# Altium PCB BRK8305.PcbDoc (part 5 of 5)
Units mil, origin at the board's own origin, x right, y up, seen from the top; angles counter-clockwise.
Board outline 5944.89 x 4139.76 mil, 4 copper layers (L1-Top, L2-GND, L3-GND, L4-BOT), stack 61.2 mil thick; 237 components, 286 nets, 1257 pads, 698 vias.
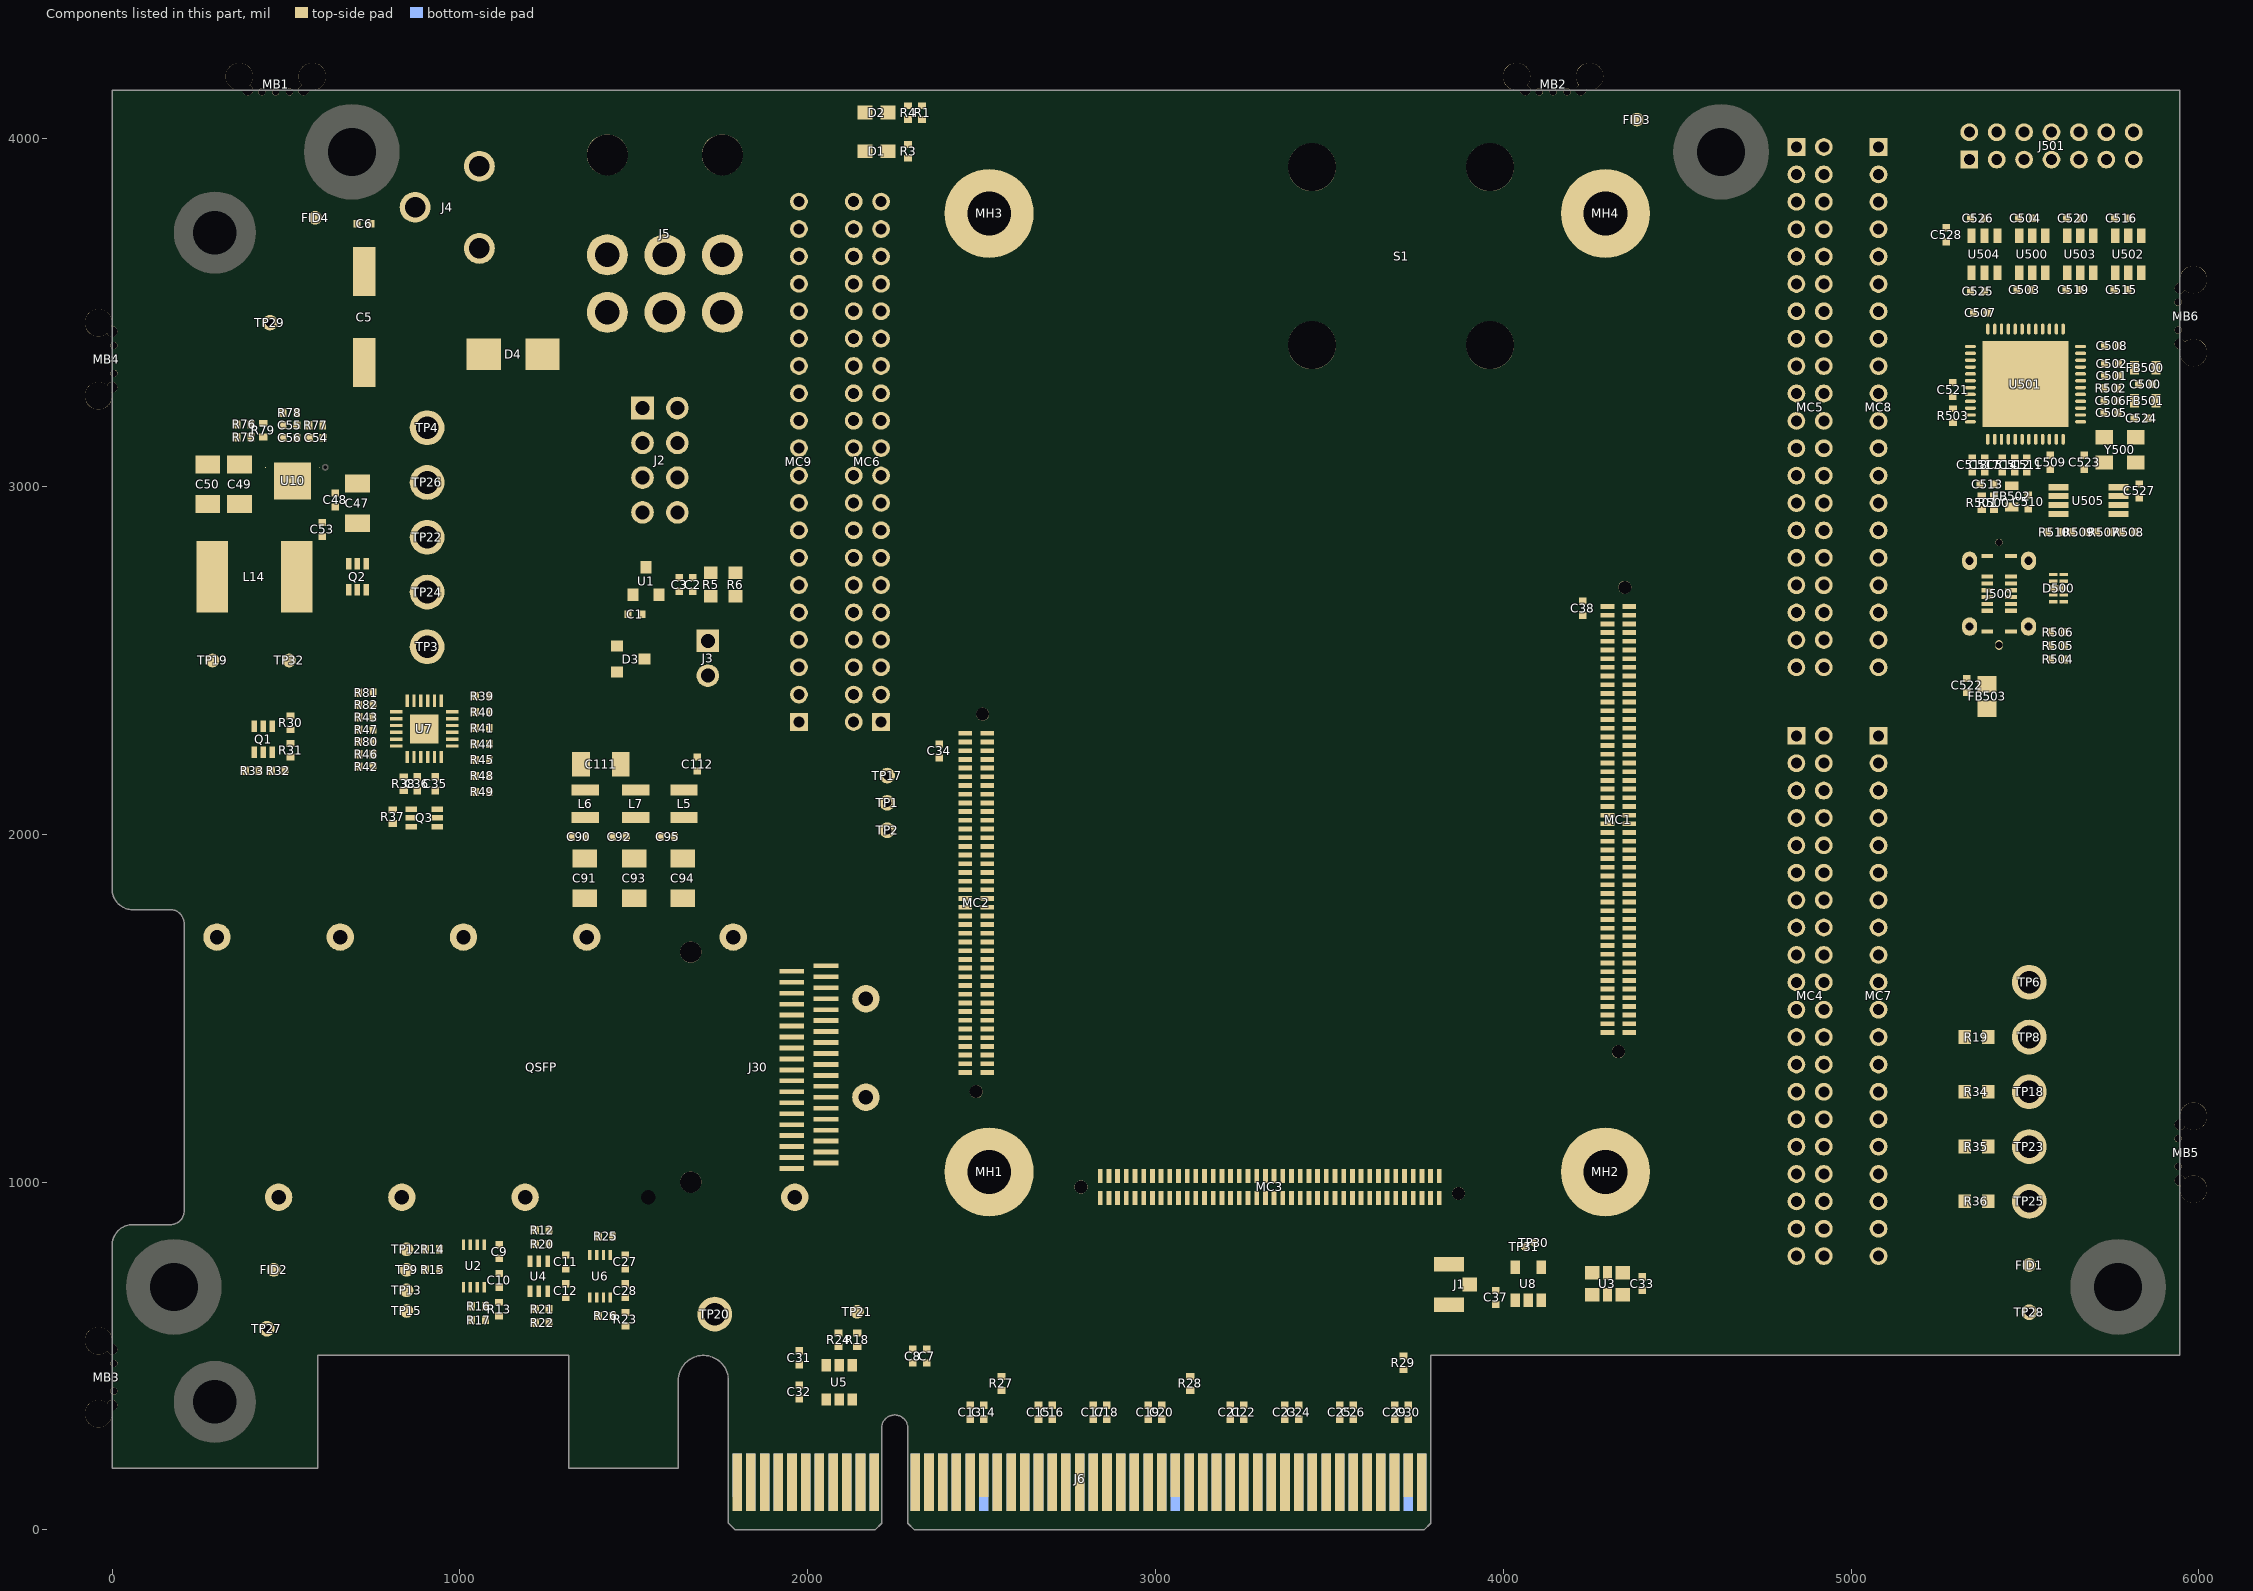
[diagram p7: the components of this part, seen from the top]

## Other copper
L1-Top:
  region net DGND: 1188.23,3425.29 1218.2,3425.29 1254.13,3461.22 1324.92,3461.22 1334.65,3451.49 1334.65,3301.57 1324.5,3291.43 1259.84,3291.43 1216.54,3334.74 1188.23,3334.74
  region net +VDCIN: 670.7,3503.97 775.77,3503.97 804.57,3532.77 804.57,3701.38 777.24,3728.7 670.04,3728.7 643.16,3701.82 643.16,3531.51
  region net NetC53_2: 614.15,2638.61 614.15,2865.61 595.15,2865.61 538.96,2921.81 538.96,2953.61 474,2953.61 474,2638.61
  region net DGND: 560.67,3058.65 560.67,2972.36 414.15,2972.36 414.15,3009.76 480.28,3009.76 480.28,3058.65
  region net +VDCIN: 740.15,3067.61 631.15,3067.61 631.15,3036.34 579.69,3036.34 579.69,2971.38 740.15,2971.38
  region net DGND: 670.7,3242.15 775.77,3242.15 804.57,3270.96 804.57,3439.57 777.24,3466.89 670.04,3466.89 643.16,3440.01 643.16,3269.7
L4-BOT:
  pour cut-out: 1056.58,3755.47 cw(c1056.58,3684.6) 1127.44,3684.6 cw(c1056.58,3684.6) 1056.58,3613.73 cw(c1056.58,3684.6) 985.71,3684.6 cw(c1056.58,3684.6)

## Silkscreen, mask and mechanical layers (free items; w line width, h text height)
Top Overlay:
  circle w22: c1122.85,3569.62 r11
  region: 5877.95,1994.09 5216.95,1994.09 5216.95,1679.13 5877.95,1679.13
  lines w10: 2364.17,2188.98 2364.17,872.05 4450.79,872.05 4450.79,4118.11 ; 2364.17,2291.34 2364.17,4118.11
  lines w15.75: 1034.85,3569.62 1082.85,3569.62 ; 1122.85,3569.62 1184.85,3569.62 ; 1136.53,3532.03 cw(c1122.85,3569.62) 1136.53,3607.2
  lines w20: 5253.94,1102.36 5285.43,1102.36 ; 5253.94,1259.84 5285.43,1259.84 ; 5253.94,1417.32 5285.43,1417.32 ; 5285.43,944.88 5253.94,944.88 5253.94,1525.59 5303.15,1574.8 5437.01,1574.8 ; 5431.1,944.88 5444.88,944.88 ; 5431.1,1102.36 5444.88,1102.36 ; 5431.1,1258.78 5444.88,1258.78 ; 5431.1,1417.32 5444.88,1417.32
  text "DGND" at 5137.8,3996.68 h30 r270
  text "5-15 VDC" at 293.89,3912 h100
  text "JTAG HEADER" at 5375.38,3791.32 h60
  text "+" at 1197.85,3608.61 h70 r270
  text "-" at 942.85,3534.62 h70
  text "TESTING ONLY" at 3581.9,3449.8 h60
  text "SYSMON" at 1423.07,3342.72 h80
  text "VP" at 1386.71,3204.88 h50
  text "VCCADC" at 1687.88,3198.9 h50
  text "VN" at 1385.76,3104.88 h50
  text "GNDADC" at 1252.66,2904.88 h50
  text "VREFP" at 1687.88,2898.9 h50
  text "USB JTAG" at 5295.23,2463.78 h100 r90
  text "+" at 1838.09,2305.77 h80 r90
  text "DGND" at 5137.8,2303.77 h30 r270
  text "DGND" at 1917.32,2296.4 h30 r90
  text "'.Part_Number' '.PCB_Revision'XX" at 5343.85,2039.5 h40
  text "3V3" at 3731.33,760.22 h40 r270
  text "224 REFCLK0" at 3776.41,549.9 h60
Top Solder:
  rectangle: 1312.98,177.16 1627.94,312.99
Solder Side:
  rectangle: 1312.98,177.16 1627.94,312.99
Dimensions:
  rectangle: 1781.49,9.84 3781.49,56.93
  lines w1: 4526.47,-267.17 4547.19,-321.84 4567.68,-321.84 4588.52,-266.87 ; 4526.83,-267.19 4526.83,28.16
  lines w2: 4588.43,-266.84 4588.43,-25.42 ; 4638.85,-134.01 4687.73,-5.23
  lines w10: 3781.49,9.84 4220.47,-515.75 ; 3781.49,56.93 4343.78,350.39 ; 5349.4,-145.34 cw(c4724.4,-145.34) 5349.4,-143.92
  text "EDGE BEVEL" at 4455.01,340.55 h50
  text "ACROSS PADS" at 4586.74,-588.49 h50
  text "ALL UNITS IN MILLIMETERS UNLESS OTHERWISE SPECIFIED" at 708.66,-629.92 h60
Outline:
  lines w3.94: -0.01,177.16 -0.01,818.9 cw(c59.06,818.9) 59.06,877.95 167.46,877.95 ccw(c167.46,917.32) 206.83,917.32 206.83,1744.09 ccw(c167.46,1744.09) 167.46,1783.46 59.06,1783.46 cw(c59.06,1842.52) 0,1842.52 -0.01,4139.76 5944.88,4139.76 5944.88,501.97 3791.33,501.97 3791.33,19.68 3771.65,0 2307.08,0 2287.39,19.68 2287.39,293.31 ccw(c2249.99,293.31) 2212.59,293.31 2212.59,19.68 2192.91,0 1791.33,0 1771.65,19.68 1771.65,430.12 ccw(c1699.8,430.12) 1627.94,430.12 1627.94,177.16 1312.98,177.16 1312.98,501.97 590.54,501.97 590.54,177.16 -0.01,177.16
  lines w11.81: 2364.17,872.05 2364.17,4139.76 4450.79,4139.76 4450.79,872.05 2364.17,872.05
Fab Notes:
  drawing of 90 lines, arcs and shapes, not listed
  text "LAYER STACKUP TABLE" at 7244.09,7330.71 h80
  text "S" at 12600.61,7229.28 h79.46
  text "i" at 12632.47,7229.28 h79.46
  text "n" at 12650.67,7229.28 h79.46
  text "g" at 12687.08,7229.27 h79.46
  text "l" at 12718.94,7229.28 h79.46
  text "e" at 12737.14,7229.28 h79.46
  text "-" at 12773.55,7229.3 h79.46
  text "D" at 10138.59,7138.26 h79.46
  text "i" at 10179.55,7138.26 h79.46
  text "f" at 10197.75,7138.26 h79.46
  text "f" at 10220.51,7138.26 h79.46
  text "e" at 10243.26,7138.26 h79.46
  text "r" at 10279.67,7138.26 h79.46
  text "e" at 10302.43,7138.26 h79.46
  text "n" at 10338.83,7138.26 h79.46
  text "t" at 10375.24,7138.26 h79.46
  text "i" at 10398,7138.26 h79.46
  text "a" at 10416.2,7138.26 h79.46
  text "l" at 10448.06,7138.26 h79.46
  text "D" at 10515.61,7138.26 h79.46
  text "i" at 10556.57,7138.26 h79.46
  text "f" at 10574.78,7138.26 h79.46
  text "f" at 10597.53,7138.26 h79.46
  text "e" at 10620.29,7138.26 h79.46
  text "r" at 10656.7,7138.26 h79.46
  text "e" at 10679.45,7138.26 h79.46
  text "n" at 10715.86,7138.26 h79.46
  text "t" at 10752.27,7138.26 h79.46
  text "i" at 10775.02,7138.26 h79.46
  text "a" at 10793.23,7138.26 h79.46
  text "l" at 10825.08,7138.26 h79.46
  text "D" at 10938.06,7138.26 h79.46
  text "i" at 10979.02,7138.26 h79.46
  text "f" at 10997.23,7138.26 h79.46
  text "f" at 11019.98,7138.26 h79.46
  text "e" at 11042.74,7138.26 h79.46
  text "r" at 11079.15,7138.26 h79.46
  text "e" at 11101.9,7138.26 h79.46
  text "n" at 11138.31,7138.26 h79.46
  text "t" at 11174.72,7138.26 h79.46
  text "i" at 11197.47,7138.26 h79.46
  text "a" at 11215.68,7138.26 h79.46
  text "l" at 11247.53,7138.26 h79.46
  text "D" at 11315.09,7138.26 h79.46
  text "i" at 11356.05,7138.26 h79.46
  text "f" at 11374.25,7138.26 h79.46
  text "f" at 11397.01,7138.26 h79.46
  text "e" at 11419.76,7138.26 h79.46
  text "r" at 11456.17,7138.26 h79.46
  text "e" at 11478.93,7138.26 h79.46
  text "n" at 11515.33,7138.26 h79.46
  text "t" at 11551.74,7138.26 h79.46
  text "i" at 11574.5,7138.26 h79.46
  text "a" at 11592.7,7138.26 h79.46
  text "l" at 11624.56,7138.26 h79.46
  text "D" at 11737.54,7138.26 h79.46
  text "i" at 11778.5,7138.26 h79.46
  text "f" at 11796.7,7138.26 h79.46
  text "f" at 11819.46,7138.26 h79.46
  text "e" at 11842.21,7138.26 h79.46
  text "r" at 11878.62,7138.26 h79.46
  text "e" at 11901.38,7138.26 h79.46
  text "n" at 11937.78,7138.26 h79.46
  text "t" at 11974.19,7138.26 h79.46
  text "i" at 11996.95,7138.26 h79.46
  text "a" at 12015.15,7138.26 h79.46
  text "l" at 12047.01,7138.26 h79.46
  text "D" at 12114.56,7138.26 h79.46
  text "i" at 12155.52,7138.26 h79.46
  text "f" at 12173.73,7138.26 h79.46
  text "f" at 12196.48,7138.26 h79.46
  text "e" at 12219.24,7138.26 h79.46
  text "r" at 12255.65,7138.26 h79.46
  text "e" at 12278.4,7138.26 h79.46
  text "n" at 12314.81,7138.26 h79.46
  text "t" at 12351.22,7138.26 h79.46
  text "i" at 12373.97,7138.26 h79.46
  text "a" at 12392.18,7138.26 h79.46
  text "l" at 12424.03,7138.26 h79.46
  text "E" at 12609.69,7138.26 h79.46
  text "n" at 12641.55,7138.26 h79.46
  text "d" at 12677.96,7138.26 h79.46
  text "e" at 12714.37,7138.26 h79.46
  text "d" at 12750.78,7138.26 h79.46
  text "T" at 10229.44,7047.24 h79.46
  text "r" at 10261.3,7047.24 h79.46
  text "a" at 10284.05,7047.24 h79.46
  text "c" at 10315.91,7047.24 h79.46
  text "e" at 10343.21,7047.24 h79.46
  text "T" at 10606.46,7047.24 h79.46
  text "r" at 10638.32,7047.24 h79.46
  text "a" at 10661.08,7047.24 h79.46
  text "c" at 10692.93,7047.24 h79.46
  text "e" at 10720.24,7047.24 h79.46
  text "T" at 11028.91,7047.24 h79.46
  text "r" at 11060.77,7047.24 h79.46
  text "a" at 11083.53,7047.24 h79.46
  text "c" at 11115.38,7047.24 h79.46
  text "e" at 11142.69,7047.24 h79.46
  text "T" at 11405.94,7047.24 h79.46
  text "r" at 11437.8,7047.24 h79.46
  text "a" at 11460.55,7047.24 h79.46
  text "c" at 11492.41,7047.24 h79.46
  text "e" at 11519.71,7047.24 h79.46
  text "T" at 11828.39,7047.24 h79.46
  text "r" at 11860.25,7047.24 h79.46
  text "a" at 11883,7047.24 h79.46
  text "c" at 11914.86,7047.24 h79.46
  text "e" at 11942.16,7047.24 h79.46
  text "T" at 12205.41,7047.24 h79.46
  text "r" at 12237.27,7047.24 h79.46
  text "a" at 12260.03,7047.24 h79.46
  text "c" at 12291.88,7047.24 h79.46
  text "e" at 12319.19,7047.24 h79.46
  text "T" at 12623.32,7047.24 h79.46
  text "r" at 12655.18,7047.24 h79.46
  text "a" at 12677.93,7047.24 h79.46
  text "c" at 12709.79,7047.24 h79.46
  text "e" at 12737.1,7047.24 h79.46
  text "S" at 12891.33,7047.24 h79.46
  text "i" at 12923.18,7047.24 h79.46
  text "n" at 12941.39,7047.24 h79.46
  text "g" at 12977.8,7047.23 h79.46
  text "l" at 13009.65,7047.24 h79.46
  text "e" at 13027.86,7047.24 h79.46
  text "-" at 13064.27,7047.26 h79.46
  text "E" at 13087.02,7047.24 h79.46
  text "n" at 13118.88,7047.24 h79.46
  text "d" at 13155.29,7047.24 h79.46
  text "e" at 13191.69,7047.24 h79.46
  text "d" at 13228.1,7047.24 h79.46
  text "M" at 9357.28,7045.9 h75.05
  text "a" at 9407.35,7045.9 h75.05
  text "t" at 9443.75,7045.9 h75.05
  text "e" at 9461.96,7045.9 h75.05
  text "r" at 9498.37,7045.9 h75.05
  text "i" at 9521.12,7045.9 h75.05
  text "a" at 9534.77,7045.9 h75.05
  text "l" at 9571.18,7045.9 h75.05
  text "G" at 8089.94,6959.43 h75.05
  text "e" at 8140,6959.43 h75.05
  text "r" at 8176.41,6959.43 h75.05
  text "b" at 8199.16,6959.43 h75.05
  text "e" at 8235.57,6959.43 h75.05
  text "r" at 8271.98,6959.43 h75.05
  text "M" at 8830.36,6959.43 h75.05
  text "a" at 8880.42,6959.43 h75.05
  text "t" at 8916.83,6959.43 h75.05
  text "e" at 8935.03,6959.43 h75.05
  text "r" at 8971.44,6959.43 h75.05
  text "i" at 8994.2,6959.43 h75.05
  text "a" at 9007.85,6959.43 h75.05
  text "l" at 9044.26,6959.43 h75.05
  text "T" at 9316.4,6959.43 h75.05
  text "h" at 9357.36,6959.43 h75.05
  text "i" at 9393.77,6959.43 h75.05
  text "c" at 9407.42,6959.43 h75.05
  text "k" at 9443.83,6959.43 h75.05
  text "n" at 9475.69,6959.43 h75.05
  text "e" at 9512.1,6959.43 h75.05
  text "s" at 9548.51,6959.43 h75.05
  text "s" at 9584.91,6959.43 h75.05
  text "C" at 9766.11,6956.22 h79.46
  text "o" at 9802.52,6956.22 h79.46
  text "p" at 9838.92,6956.21 h79.46
  text "p" at 9875.33,6956.21 h79.46
  text "e" at 9911.74,6956.22 h79.46
  text "r" at 9948.15,6956.22 h79.46
  text "I" at 10147.67,6956.22 h79.46
  text "m" at 10165.88,6956.22 h79.46
  text "p" at 10220.49,6956.21 h79.46
  text "e" at 10256.9,6956.22 h79.46
  text "d" at 10293.31,6956.22 h79.46
  text "a" at 10329.72,6956.22 h79.46
  text "n" at 10361.57,6956.22 h79.46
  text "c" at 10397.98,6956.22 h79.46
  text "e" at 10425.29,6956.22 h79.46
  text "W" at 10497.44,6956.22 h79.46
  text "i" at 10556.61,6956.22 h79.46
  text "d" at 10574.81,6956.22 h79.46
  text "t" at 10611.22,6956.22 h79.46
  text "h" at 10633.98,6956.22 h79.46
  text "/" at 10670.38,6956.21 h79.46
  text "S" at 10697.69,6956.22 h79.46
  text "p" at 10729.55,6956.21 h79.46
  text "a" at 10765.96,6956.22 h79.46
  text "c" at 10797.81,6956.22 h79.46
  text "e" at 10825.12,6956.22 h79.46
  text "I" at 10947.15,6956.22 h79.46
  text "m" at 10965.35,6956.22 h79.46
  text "p" at 11019.97,6956.21 h79.46
  text "e" at 11056.37,6956.22 h79.46
  text "d" at 11092.78,6956.22 h79.46
  text "a" at 11129.19,6956.22 h79.46
  text "n" at 11161.05,6956.22 h79.46
  text "c" at 11197.46,6956.22 h79.46
  text "e" at 11224.76,6956.22 h79.46
  text "W" at 11296.92,6956.22 h79.46
  text "i" at 11356.08,6956.22 h79.46
  text "d" at 11374.29,6956.22 h79.46
  text "t" at 11410.7,6956.22 h79.46
  text "h" at 11433.45,6956.22 h79.46
  text "/" at 11469.86,6956.21 h79.46
  text "S" at 11497.16,6956.22 h79.46
  text "p" at 11529.02,6956.21 h79.46
  text "a" at 11565.43,6956.22 h79.46
  text "c" at 11597.29,6956.22 h79.46
  text "e" at 11624.59,6956.22 h79.46
  text "I" at 11746.62,6956.22 h79.46
  text "m" at 11764.83,6956.22 h79.46
  text "p" at 11819.44,6956.21 h79.46
  text "e" at 11855.85,6956.22 h79.46
  text "d" at 11892.26,6956.22 h79.46
  text "a" at 11928.67,6956.22 h79.46
  text "n" at 11960.52,6956.22 h79.46
  text "c" at 11996.93,6956.22 h79.46
  text "e" at 12024.24,6956.22 h79.46
  text "W" at 12096.39,6956.22 h79.46
  text "i" at 12155.56,6956.22 h79.46
  text "d" at 12173.76,6956.22 h79.46
  text "t" at 12210.17,6956.22 h79.46
  text "h" at 12232.93,6956.22 h79.46
  text "/" at 12269.33,6956.21 h79.46
  text "S" at 12296.64,6956.22 h79.46
  text "p" at 12328.5,6956.21 h79.46
  text "a" at 12364.9,6956.22 h79.46
  text "c" at 12396.76,6956.22 h79.46
  text "e" at 12424.07,6956.22 h79.46
  text "I" at 12541.56,6956.22 h79.46
  text "m" at 12559.76,6956.22 h79.46
  text "p" at 12614.37,6956.21 h79.46
  text "e" at 12650.78,6956.22 h79.46
  text "d" at 12687.19,6956.22 h79.46
  text "a" at 12723.6,6956.22 h79.46
  text "n" at 12755.45,6956.22 h79.46
  text "c" at 12791.86,6956.22 h79.46
  text "e" at 12819.17,6956.22 h79.46
  text "T" at 12909.5,6956.22 h79.46
  text "r" at 12941.35,6956.22 h79.46
  text "a" at 12964.11,6956.22 h79.46
  text "c" at 12995.97,6956.22 h79.46
  text "e" at 13023.27,6956.22 h79.46
  text "W" at 13073.33,6956.22 h79.46
  text "i" at 13132.5,6956.22 h79.46
  text "d" at 13150.7,6956.22 h79.46
  text "t" at 13187.11,6956.22 h79.46
  text "h" at 13209.86,6956.22 h79.46
  text "L" at 7217.78,6872.96 h75.05
  text "a" at 7254.19,6872.96 h75.05
  text "y" at 7290.6,6872.95 h75.05
  text "e" at 7322.46,6872.96 h75.05
  text "r" at 7358.86,6872.96 h75.05
  text "L" at 7444.91,6872.96 h75.05
  text "a" at 7481.31,6872.96 h75.05
  text "y" at 7517.72,6872.95 h75.05
  text "e" at 7549.58,6872.96 h75.05
  text "r" at 7585.99,6872.96 h75.05
  text "N" at 7626.95,6872.96 h75.05
  text "a" at 7672.46,6872.96 h75.05
  text "m" at 7708.86,6872.96 h75.05
  text "e" at 7768.03,6872.96 h75.05
  text "L" at 8089.94,6872.96 h75.05
  text "a" at 8126.34,6872.96 h75.05
  text "y" at 8162.75,6872.95 h75.05
  text "e" at 8194.61,6872.96 h75.05
  text "r" at 8231.02,6872.96 h75.05
  text "M" at 8362.48,6872.96 h75.05
  text "a" at 8412.55,6872.96 h75.05
  text "t" at 8448.95,6872.96 h75.05
  text "e" at 8467.16,6872.96 h75.05
  text "r" at 8503.57,6872.96 h75.05
  text "i" at 8526.32,6872.96 h75.05
  text "a" at 8539.97,6872.96 h75.05
  text "l" at 8576.38,6872.96 h75.05
  text "T" at 8608.24,6872.96 h75.05
  text "y" at 8649.2,6872.95 h75.05
  text "p" at 8681.06,6872.95 h75.05
  text "e" at 8717.46,6872.96 h75.05
  text "C" at 8830.36,6872.96 h75.05
  text "o" at 8880.42,6872.96 h75.05
  text "n" at 8916.83,6872.96 h75.05
  text "s" at 8953.24,6872.96 h75.05
  text "t" at 8989.64,6872.96 h75.05
  text "r" at 9007.85,6872.96 h75.05
  text "u" at 9030.6,6872.96 h75.05
  text "c" at 9067.01,6872.96 h75.05
  text "t" at 9103.42,6872.96 h75.05
  text "i" at 9121.62,6872.96 h75.05
  text "o" at 9135.28,6872.96 h75.05
  text "n" at 9171.69,6872.96 h75.05
  text "(" at 9389.08,6872.95 h75.05
  text "m" at 9411.84,6872.96 h75.05
  text "m" at 9471,6872.96 h75.05
  text ")" at 9530.16,6872.95 h75.05
  text "W" at 9702.51,6865.2 h79.46
  text "e" at 9761.68,6865.2 h79.46
  text "i" at 9798.08,6865.2 h79.46
  text "g" at 9816.29,6865.19 h79.46
  text "h" at 9848.15,6865.2 h79.46
  text "t" at 9884.55,6865.2 h79.46
  text "(" at 9920.96,6865.19 h79.46
  text "o" at 9943.72,6865.2 h79.46
  text "z" at 9980.13,6865.2 h79.46
  text ")" at 10007.43,6865.19 h79.46
  text "(" at 10202.18,6865.19 h79.46
  text "o" at 10224.94,6865.2 h79.46
  text "h" at 10261.35,6865.2 h79.46
  text "m" at 10297.76,6865.2 h79.46
  text "s" at 10352.37,6865.2 h79.46
  text ")" at 10379.67,6865.19 h79.46
  text "(" at 10597.38,6865.19 h79.46
  text "m" at 10620.13,6865.2 h79.46
  text "i" at 10674.75,6865.2 h79.46
  text "l" at 10692.95,6865.2 h79.46
  text "s" at 10711.15,6865.2 h79.46
  text ")" at 10738.46,6865.19 h79.46
  text "(" at 11001.66,6865.19 h79.46
  text "o" at 11024.41,6865.2 h79.46
  text "h" at 11060.82,6865.2 h79.46
  text "m" at 11097.23,6865.2 h79.46
  text "s" at 11151.84,6865.2 h79.46
  text ")" at 11179.15,6865.19 h79.46
  text "(" at 11396.85,6865.19 h79.46
  text "m" at 11419.61,6865.2 h79.46
  text "i" at 11474.22,6865.2 h79.46
  text "l" at 11492.43,6865.2 h79.46
  text "s" at 11510.63,6865.2 h79.46
  text ")" at 11537.94,6865.19 h79.46
  text "(" at 11801.13,6865.19 h79.46
  text "o" at 11823.89,6865.2 h79.46
  text "h" at 11860.3,6865.2 h79.46
  text "m" at 11896.71,6865.2 h79.46
  text "s" at 11951.32,6865.2 h79.46
  text ")" at 11978.62,6865.19 h79.46
  text "(" at 12196.33,6865.19 h79.46
  text "m" at 12219.08,6865.2 h79.46
  text "i" at 12273.7,6865.2 h79.46
  text "l" at 12291.9,6865.2 h79.46
  text "s" at 12310.1,6865.2 h79.46
  text ")" at 12337.41,6865.19 h79.46
  text "(" at 12600.61,6865.19 h79.46
  text "o" at 12623.36,6865.2 h79.46
  text "h" at 12659.77,6865.2 h79.46
  text "m" at 12696.18,6865.2 h79.46
  text "s" at 12750.79,6865.2 h79.46
  text ")" at 12778.1,6865.19 h79.46
  text "(" at 12995.8,6865.19 h79.46
  text "m" at 13018.56,6865.2 h79.46
  text "i" at 13073.17,6865.2 h79.46
  text "l" at 13091.37,6865.2 h79.46
  text "s" at 13109.58,6865.2 h79.46
  text ")" at 13136.89,6865.19 h79.46
  text "O" at 7444.91,6736.43 h75.05
  text "v" at 7499.52,6736.43 h75.05
  text "e" at 7531.37,6736.43 h75.05
  text "r" at 7567.78,6736.43 h75.05
  text "l" at 7590.54,6736.43 h75.05
  text "a" at 7604.19,6736.43 h75.05
  text "y" at 7640.6,6736.42 h75.05
  text "T" at 7690.66,6736.43 h75.05
  text "o" at 7731.62,6736.43 h75.05
  text "p" at 7768.03,6736.42 h75.05
  text "G" at 8089.94,6736.43 h75.05
  text "T" at 8140,6736.43 h75.05
  text "O" at 8180.96,6736.43 h75.05
  text "S" at 8362.48,6736.43 h75.05
  text "i" at 8407.99,6736.43 h75.05
  text "l" at 8421.65,6736.43 h75.05
  text "k" at 8435.3,6736.43 h75.05
  text "s" at 8467.16,6736.43 h75.05
  text "c" at 8503.57,6736.43 h75.05
  text "r" at 8539.97,6736.43 h75.05
  text "e" at 8562.73,6736.43 h75.05
  text "e" at 8599.14,6736.43 h75.05
  text "n" at 8635.55,6736.43 h75.05
  text "S" at 7444.91,6645.41 h75.05
  text "o" at 7490.42,6645.41 h75.05
  text "l" at 7526.82,6645.41 h75.05
  text "d" at 7540.48,6645.41 h75.05
  text "e" at 7576.88,6645.41 h75.05
  text "r" at 7613.29,6645.41 h75.05
  text "M" at 7654.25,6645.41 h75.05
  text "a" at 7704.31,6645.41 h75.05
  text "s" at 7740.72,6645.41 h75.05
  text "k" at 7777.13,6645.41 h75.05
  text "T" at 7827.19,6645.41 h75.05
  text "o" at 7868.15,6645.41 h75.05
  text "p" at 7904.56,6645.4 h75.05
  text "G" at 8089.94,6645.41 h75.05
  text "T" at 8140,6645.41 h75.05
  text "S" at 8180.96,6645.41 h75.05
  text "S" at 8362.48,6645.41 h75.05
  text "o" at 8407.99,6645.41 h75.05
  text "l" at 8444.4,6645.41 h75.05
  text "d" at 8458.06,6645.41 h75.05
  text "e" at 8494.46,6645.41 h75.05
  text "r" at 8530.87,6645.41 h75.05
  text "R" at 8571.83,6645.41 h75.05
  text "e" at 8621.89,6645.41 h75.05
  text "s" at 8658.3,6645.41 h75.05
  text "i" at 8694.71,6645.41 h75.05
  text "s" at 8708.36,6645.41 h75.05
  text "t" at 8744.77,6645.41 h75.05
  text "1" at 7217.78,6554.39 h75.05
  text "L" at 7444.91,6554.39 h75.05
  text "1" at 7481.31,6554.39 h75.05
  text "-" at 7517.72,6554.4 h75.05
  text "T" at 7540.48,6554.39 h75.05
  text "O" at 7581.44,6554.39 h75.05
  text "P" at 7636.05,6554.39 h75.05
  text "G" at 8089.94,6554.39 h75.05
  text "T" at 8140,6554.39 h75.05
  text "L" at 8180.96,6554.39 h75.05
  text "C" at 8362.48,6554.39 h75.05
  text "o" at 8412.55,6554.39 h75.05
  text "p" at 8448.95,6554.38 h75.05
  text "p" at 8485.36,6554.38 h75.05
  text "e" at 8521.77,6554.39 h75.05
  text "r" at 8558.18,6554.39 h75.05
  text "0" at 9697.97,6551.18 h79.46
  text "." at 9729.83,6551.18 h79.46
  text "5" at 9748.03,6551.18 h79.46
  text "+" at 9793.54,6551.18 h79.46
  text "p" at 9839.05,6551.17 h79.46
  text "l" at 9875.46,6551.18 h79.46
  text "a" at 9893.66,6551.18 h79.46
  text "t" at 9925.52,6551.18 h79.46
  text "i" at 9948.28,6551.18 h79.46
  text "n" at 9966.48,6551.18 h79.46
  text "g" at 10002.89,6551.17 h79.46
  text "8" at 10270.32,6551.18 h79.46
  text "5" at 10302.18,6551.18 h79.46
  text "7" at 10538.33,6551.18 h79.46
  text "." at 10570.18,6551.18 h79.46
  text "5" at 10588.39,6551.18 h79.46
  text "0" at 10620.25,6551.18 h79.46
  text "/" at 10665.76,6551.17 h79.46
  text "6" at 10706.72,6551.18 h79.46
  text "." at 10738.57,6551.18 h79.46
  text "0" at 10756.78,6551.18 h79.46
  text "0" at 10788.63,6551.18 h79.46
  text "9" at 11069.8,6551.18 h79.46
  text "0" at 11101.65,6551.18 h79.46
  text "5" at 11337.8,6551.18 h79.46
  text "." at 11369.66,6551.18 h79.46
  text "6" at 11387.86,6551.18 h79.46
  text "0" at 11419.72,6551.18 h79.46
  text "/" at 11465.23,6551.17 h79.46
  text "6" at 11506.19,6551.18 h79.46
  text "." at 11538.05,6551.18 h79.46
  text "0" at 11556.25,6551.18 h79.46
  text "0" at 11588.11,6551.18 h79.46
  text "1" at 11855.64,6551.18 h79.46
  text "0" at 11887.5,6551.18 h79.46
  text "0" at 11919.36,6551.18 h79.46
  text "5" at 12137.28,6551.18 h79.46
  text "." at 12169.13,6551.18 h79.46
  text "2" at 12187.34,6551.18 h79.46
  text "5" at 12219.19,6551.18 h79.46
  text "/" at 12264.71,6551.17 h79.46
  text "6" at 12305.66,6551.18 h79.46
  text "." at 12337.52,6551.18 h79.46
  text "0" at 12355.73,6551.18 h79.46
  text "0" at 12387.58,6551.18 h79.46
  text "5" at 12668.75,6551.18 h79.46
  text "0" at 12700.6,6551.18 h79.46
  text "7" at 13036.69,6551.18 h79.46
  text "." at 13068.54,6551.18 h79.46
  text "5" at 13086.75,6551.18 h79.46
  text "P" at 8362.48,6463.37 h75.05
  text "r" at 8407.99,6463.37 h75.05
  text "e" at 8430.75,6463.37 h75.05
  text "p" at 8467.16,6463.36 h75.05
  text "r" at 8503.57,6463.37 h75.05
  text "e" at 8526.32,6463.37 h75.05
  text "g" at 8562.73,6463.36 h75.05
  text "S" at 8830.36,6460.16 h79.46
  text "1" at 8862.22,6460.16 h79.46
  text "0" at 8894.07,6460.16 h79.46
  text "0" at 8925.93,6460.16 h79.46
  text "0" at 8957.79,6460.16 h79.46
  text "-" at 8989.64,6460.17 h79.46
  text "2" at 9012.4,6460.16 h79.46
  text "M" at 9044.26,6460.16 h79.46
  text "0" at 9398.17,6460.16 h79.46
  text "." at 9430.02,6460.16 h79.46
  text "1" at 9448.23,6460.16 h79.46
  text "2" at 9480.09,6460.16 h79.46
  text "3" at 9511.94,6460.16 h79.46
  text "2" at 7217.78,6372.35 h75.05
  text "L" at 7444.91,6372.35 h75.05
  text "2" at 7481.31,6372.35 h75.05
  text "-" at 7517.72,6372.36 h75.05
  text "G" at 7540.48,6372.35 h75.05
  text "N" at 7590.54,6372.35 h75.05
  text "D" at 7636.05,6372.35 h75.05
  text "G" at 8089.94,6372.35 h75.05
  text "1" at 8140,6372.35 h75.05
  text "C" at 8362.48,6372.35 h75.05
  text "o" at 8412.55,6372.35 h75.05
  text "p" at 8448.95,6372.34 h75.05
  text "p" at 8485.36,6372.34 h75.05
  text "e" at 8521.77,6372.35 h75.05
  text "r" at 8558.18,6372.35 h75.05
  text "1" at 9852.41,6369.14 h79.46
  text "C" at 8362.48,6281.33 h75.05
  text "o" at 8412.55,6281.33 h75.05
  text "r" at 8448.95,6281.33 h75.05
  text "e" at 8471.71,6281.33 h75.05
  text "1" at 9398.17,6278.12 h79.46
  text "." at 9430.02,6278.12 h79.46
  text "1" at 9448.23,6278.12 h79.46
  text "4" at 9480.09,6278.12 h79.46
  text "3" at 9511.94,6278.12 h79.46
  text "3" at 7217.78,6190.31 h75.05
  text "L" at 7444.91,6190.31 h75.05
  text "3" at 7481.31,6190.31 h75.05
  text "-" at 7517.72,6190.32 h75.05
  text "P" at 7540.48,6190.31 h75.05
  text "W" at 7585.99,6190.31 h75.05
  text "R" at 7654.25,6190.31 h75.05
  text "G" at 8089.94,6190.31 h75.05
  text "2" at 8140,6190.31 h75.05
  text "C" at 8362.48,6190.31 h75.05
  text "o" at 8412.55,6190.31 h75.05
  text "p" at 8448.95,6190.3 h75.05
  text "p" at 8485.36,6190.3 h75.05
  text "e" at 8521.77,6190.31 h75.05
  text "r" at 8558.18,6190.31 h75.05
  text "1" at 9852.41,6187.1 h79.46
  text "P" at 8362.48,6099.29 h75.05
  text "r" at 8407.99,6099.29 h75.05
  text "e" at 8430.75,6099.29 h75.05
  text "p" at 8467.16,6099.28 h75.05
  text "r" at 8503.57,6099.29 h75.05
  text "e" at 8526.32,6099.29 h75.05
  text "g" at 8562.73,6099.28 h75.05
  text "S" at 8830.36,6096.08 h79.46
  text "1" at 8862.22,6096.08 h79.46
  text "0" at 8894.07,6096.08 h79.46
  text "0" at 8925.93,6096.08 h79.46
  text "0" at 8957.79,6096.08 h79.46
  text "-" at 8989.64,6096.09 h79.46
  text "2" at 9012.4,6096.08 h79.46
  text "M" at 9044.26,6096.08 h79.46
  text "0" at 9398.17,6096.08 h79.46
  text "." at 9430.02,6096.08 h79.46
  text "1" at 9448.23,6096.08 h79.46
  text "2" at 9480.09,6096.08 h79.46
  text "3" at 9511.94,6096.08 h79.46
  text "4" at 7217.78,6008.27 h75.05
  text "L" at 7444.91,6008.27 h75.05
  text "4" at 7481.31,6008.27 h75.05
  text "-" at 7517.72,6008.28 h75.05
  text "B" at 7540.48,6008.27 h75.05
  text "O" at 7585.99,6008.27 h75.05
  text "T" at 7640.6,6008.27 h75.05
  text "G" at 8089.94,6008.27 h75.05
  text "B" at 8140,6008.27 h75.05
  text "L" at 8185.51,6008.27 h75.05
  text "C" at 8362.48,6008.27 h75.05
  text "o" at 8412.55,6008.27 h75.05
  text "p" at 8448.95,6008.26 h75.05
  text "p" at 8485.36,6008.26 h75.05
  text "e" at 8521.77,6008.27 h75.05
  text "r" at 8558.18,6008.27 h75.05
  text "0" at 9697.97,6005.06 h79.46
  text "." at 9729.83,6005.06 h79.46
  text "5" at 9748.03,6005.06 h79.46
  text "+" at 9793.54,6005.06 h79.46
  text "p" at 9839.05,6005.05 h79.46
  text "l" at 9875.46,6005.06 h79.46
  text "a" at 9893.66,6005.06 h79.46
  text "t" at 9925.52,6005.06 h79.46
  text "i" at 9948.28,6005.06 h79.46
  text "n" at 9966.48,6005.06 h79.46
  text "g" at 10002.89,6005.05 h79.46
  text "8" at 10270.32,6005.06 h79.46
  text "5" at 10302.18,6005.06 h79.46
  text "7" at 10538.33,6005.06 h79.46
  text "." at 10570.18,6005.06 h79.46
  text "5" at 10588.39,6005.06 h79.46
  text "0" at 10620.25,6005.06 h79.46
  text "/" at 10665.76,6005.05 h79.46
  text "6" at 10706.72,6005.06 h79.46
  text "." at 10738.57,6005.06 h79.46
  text "0" at 10756.78,6005.06 h79.46
  text "0" at 10788.63,6005.06 h79.46
  text "9" at 11069.8,6005.06 h79.46
  text "0" at 11101.65,6005.06 h79.46
  text "5" at 11337.8,6005.06 h79.46
  text "." at 11369.66,6005.06 h79.46
  text "6" at 11387.86,6005.06 h79.46
  text "0" at 11419.72,6005.06 h79.46
  text "/" at 11465.23,6005.05 h79.46
  text "6" at 11506.19,6005.06 h79.46
  text "." at 11538.05,6005.06 h79.46
  text "0" at 11556.25,6005.06 h79.46
  text "0" at 11588.11,6005.06 h79.46
  text "1" at 11855.64,6005.06 h79.46
  text "0" at 11887.5,6005.06 h79.46
  text "0" at 11919.36,6005.06 h79.46
  text "5" at 12137.28,6005.06 h79.46
  text "." at 12169.13,6005.06 h79.46
  text "2" at 12187.34,6005.06 h79.46
  text "5" at 12219.19,6005.06 h79.46
  text "/" at 12264.71,6005.05 h79.46
  text "6" at 12305.66,6005.06 h79.46
  text "." at 12337.52,6005.06 h79.46
  text "0" at 12355.73,6005.06 h79.46
  text "0" at 12387.58,6005.06 h79.46
  text "5" at 12668.75,6005.06 h79.46
  text "0" at 12700.6,6005.06 h79.46
  text "7" at 13036.69,6005.06 h79.46
  text "." at 13068.54,6005.06 h79.46
  text "5" at 13086.75,6005.06 h79.46
  text "S" at 7444.91,5917.25 h75.05
  text "o" at 7490.42,5917.25 h75.05
  text "l" at 7526.82,5917.25 h75.05
  text "d" at 7540.48,5917.25 h75.05
  text "e" at 7576.88,5917.25 h75.05
  text "r" at 7613.29,5917.25 h75.05
  text "M" at 7654.25,5917.25 h75.05
  text "a" at 7704.31,5917.25 h75.05
  text "s" at 7740.72,5917.25 h75.05
  text "k" at 7777.13,5917.25 h75.05
  text "B" at 7827.19,5917.25 h75.05
  text "o" at 7872.7,5917.25 h75.05
  text "t" at 7909.11,5917.25 h75.05
  text "t" at 7927.31,5917.25 h75.05
  text "o" at 7945.52,5917.25 h75.05
  text "m" at 7981.93,5917.25 h75.05
  text "G" at 8089.94,5917.25 h75.05
  text "B" at 8140,5917.25 h75.05
  text "S" at 8185.51,5917.25 h75.05
  text "S" at 8362.48,5917.25 h75.05
  text "o" at 8407.99,5917.25 h75.05
  text "l" at 8444.4,5917.25 h75.05
  text "d" at 8458.06,5917.25 h75.05
  text "e" at 8494.46,5917.25 h75.05
  text "r" at 8530.87,5917.25 h75.05
  text "R" at 8571.83,5917.25 h75.05
  text "e" at 8621.89,5917.25 h75.05
  text "s" at 8658.3,5917.25 h75.05
  text "i" at 8694.71,5917.25 h75.05
  text "s" at 8708.36,5917.25 h75.05
  text "t" at 8744.77,5917.25 h75.05
  text "O" at 7444.91,5826.23 h75.05
  text "v" at 7499.52,5826.23 h75.05
  text "e" at 7531.37,5826.23 h75.05
  text "r" at 7567.78,5826.23 h75.05
  text "l" at 7590.54,5826.23 h75.05
  text "a" at 7604.19,5826.23 h75.05
  text "y" at 7640.6,5826.21 h75.05
  text "B" at 7690.66,5826.23 h75.05
  text "o" at 7736.17,5826.23 h75.05
  text "t" at 7772.58,5826.23 h75.05
  text "t" at 7790.78,5826.23 h75.05
  text "o" at 7808.99,5826.23 h75.05
  text "m" at 7845.4,5826.23 h75.05
  text "G" at 8089.94,5826.23 h75.05
  text "B" at 8140,5826.23 h75.05
  text "O" at 8185.51,5826.23 h75.05
  text "S" at 8362.48,5826.23 h75.05
  text "i" at 8407.99,5826.23 h75.05
  text "l" at 8421.65,5826.23 h75.05
  text "k" at 8435.3,5826.23 h75.05
  text "s" at 8467.16,5826.23 h75.05
  text "c" at 8503.57,5826.23 h75.05
  text "r" at 8539.97,5826.23 h75.05
  text "e" at 8562.73,5826.23 h75.05
  text "e" at 8599.14,5826.23 h75.05
  text "n" at 8635.55,5826.23 h75.05
  text "NOTES: /  / 1. MATERIAL: /    S1000-2M or equivalent /    Surface finish: ENIG /    Overall thickness: 62 mils +/-10% /  / 2. Fabricate to IPC-6012 (latest revision), Class 2 /  / 3. SOLDER RESIST: Blue LPI applied over bare copper or gold/nickel plating /  / 4. SILKSCREEN: White /  / 5. All vendor markings must be on bottom side of PCB /  / 6. LOT CODE IDENTIFICATION: /    Supplier must add identifier and lot code date to silkscreen. /    LOT CODE DATE FORMAT: YYWW (YY = 2-digit year, WW = 2-digit week) /  / 7. Drill sizes are finished size after plating /  / 8. 100% electrical bare board test required for continuity /  / 9. IMPEDANCE CONTROL: /    See Layer Stackup Table on this drawing and refer to '.Part_Number'-PCBStackup.pdf /  / 10. PANELIZATION: /    2 pieces per array /    Tab routing required. Tab locations indicated by mouse bite hole features on PCB edge /    See mouse bite drawing in fab notes for tab design details /    OUTLINE DIMENSION TOLERANCE: +/-0.127 mm /    0.25-inch rails on all sides /  / 11. POFV: All 10-mil diameter vias must be filled using non-conductive epoxy and plated over. /  / 12. ROHS: Fabricate to meet EU RoHS directive. Supplier must add lead-free marking in silkscreen. /  / 13. UL: Supplier must add UL certification marking (94V-0) in silkscreen. /  / 14. Remove all non-functional pads from internal layers /  / 15. PCIE fingers must be plated with 30 micro inches of hard gold" at 9043.31,2976.38 h38
  text "Mouse Bite Drawing" at 9834.5,2813.16 h80
  text "Connections between multiple panel boards must mirror the hole pattern on both sides" at 9906.5,2618.51 h30
  text "PCB Edge" at 9683.15,2069.94 h55
  text "0.00 Mil" at 10431.01,1663.48 h40 r90
  text "40.00 Mil" at 10490.06,1623.49 h40 r90
  text "160.00 Mil" at 10596.36,1590.17 h40 r90
Assy Notes Top:
  text "NOTES /  / 1. SOLDER QSFP CAGE IN FOUR PLACES ON BOTTOM SIDE AS INDICATED." at -1609.25,4984.07 h50
Mechanical 7:
  circle w10: c1961.12,955.13 r74.01
  circle w10: c476.87,955.13 r74.01
  circle w10: c299.71,1703.16 r74.01
  circle w10: c1783.96,1703.16 r74.01
  lines w10: -115.21,1847.31 164.98,1847.31 249.98,1762.31
  text "SOLDER ON BOTTOM SIDE" at -141.73,1648.62 h60
Drill Drawing:
  drawing of 184 lines, arcs and shapes, not listed
  text "DRILL TABLE" at 8586.61,1358.27 h50
  text "Symbol" at 8624.06,1255.88 h49.06
  text "Count" at 8972.57,1255.88 h49.06
  text "Hole Size" at 9410.93,1255.88 h49.06
  text "Plated" at 10196.72,1255.88 h49.06
  text "Drill Layer Pair" at 10545.23,1255.88 h49.06
  text "Via/Pad" at 11359.69,1255.88 h49.06
  text "Hole Tolerance" at 11765.42,1255.88 h49.06
  text "700" at 8972.57,1153.67 h40.89
  text "10.00mil (0.254mm)" at 9410.93,1153.67 h40.89
  text "PTH" at 10196.72,1153.67 h40.89
  text "L1-Top - L4-BOT" at 10545.23,1153.67 h40.89
  text "(Mixed)" at 11359.69,1153.67 h40.89
  text "+/-3.00mil" at 11765.42,1153.67 h40.89
  text "18" at 8972.57,1051.46 h40.89
  text "20.00mil (0.508mm)" at 9410.93,1051.46 h40.89
  text "NPTH" at 10196.72,1051.46 h40.89
  text "L1-Top - L4-BOT" at 10545.23,1051.46 h40.89
  text "Pad" at 11359.69,1051.46 h40.89
  text "+/-3.00mil" at 11765.42,1051.46 h40.89
  text "D" at 8603.42,1043.46 h45.43
  text "1" at 8972.57,949.24 h40.89
  text "20.47mil (0.520mm)" at 9410.93,949.24 h40.89
  text "NPTH" at 10196.72,949.24 h40.89
  text "L1-Top - L4-BOT" at 10545.23,949.24 h40.89
  text "Pad" at 11359.69,949.24 h40.89
  text "+/-3.00mil" at 11765.42,949.24 h40.89
  text "1" at 8972.57,847.03 h40.89
  text "20.47mil (0.520mm)" at 9410.93,847.03 h40.89
  text "NPTH" at 10196.72,847.03 h40.89
  text "L1-Top - L4-BOT" at 10545.23,847.03 h40.89
  text "Pad" at 11359.69,847.03 h40.89
  text "+/-3.00mil" at 11765.42,847.03 h40.89
  text "B" at 8603.42,839.03 h45.43
  text "4" at 8972.57,744.81 h40.89
  text "23.62mil (0.600mm)" at 9410.93,744.81 h40.89
  text "PTH" at 10196.72,744.81 h40.89
  text "L1-Top - L4-BOT" at 10545.23,744.81 h40.89
  text "Pad" at 11359.69,744.81 h40.89
  text "+/-3.00mil" at 11765.42,744.81 h40.89
  text "A" at 8603.42,736.82 h45.43
  text "6" at 8972.57,642.6 h40.89
  text "25.00mil (0.635mm)" at 9410.93,642.6 h40.89
  text "PTH" at 10196.72,642.6 h40.89
  text "L1-Top - L4-BOT" at 10545.23,642.6 h40.89
  text "Pad" at 11359.69,642.6 h40.89
  text "+/-3.00mil" at 11765.42,642.6 h40.89
  text "12" at 8972.57,540.39 h40.89
  text "30.00mil (0.762mm)" at 9410.93,540.39 h40.89
  text "NPTH" at 10196.72,540.39 h40.89
  text "L1-Top - L4-BOT" at 10545.23,540.39 h40.89
  text "Pad" at 11359.69,540.39 h40.89
  text "+/-3.00mil" at 11765.42,540.39 h40.89
  text "194" at 8972.57,438.17 h40.89
  text "31.50mil (0.800mm)" at 9410.93,438.17 h40.89
  text "PTH" at 10196.72,438.17 h40.89
  text "L1-Top - L4-BOT" at 10545.23,438.17 h40.89
  text "Pad" at 11359.69,438.17 h40.89
  text "+/-3.15mil" at 11765.42,438.17 h40.89
  text "F" at 8603.42,430.18 h45.43
  text "6" at 8972.57,335.96 h40.89
  text "37.40mil (0.950mm)" at 9410.93,335.96 h40.89
  text "NPTH" at 10196.72,335.96 h40.89
  text "L1-Top - L4-BOT" at 10545.23,335.96 h40.89
  text "Pad" at 11359.69,335.96 h40.89
  text "+/-3.00mil" at 11765.42,335.96 h40.89
  text "8" at 8972.57,233.74 h40.89
  text "40.00mil (1.016mm)" at 9410.93,233.74 h40.89
  text "PTH" at 10196.72,233.74 h40.89
  text "L1-Top - L4-BOT" at 10545.23,233.74 h40.89
  text "Pad" at 11359.69,233.74 h40.89
  text "+/-3.00mil" at 11765.42,233.74 h40.89
  text "I" at 8610.99,225.75 h45.43
  text "2" at 8972.57,131.53 h40.89
  text "40.16mil (1.020mm)" at 9410.93,131.53 h40.89
  text "PTH" at 10196.72,131.53 h40.89
  text "L1-Top - L4-BOT" at 10545.23,131.53 h40.89
  text "Pad" at 11359.69,131.53 h40.89
  text "+/-3.00mil" at 11765.42,131.53 h40.89
  text "1" at 8972.57,29.32 h40.89
  text "41.34mil (1.050mm)" at 9410.93,29.32 h40.89
  text "NPTH" at 10196.72,29.32 h40.89
  text "L1-Top - L4-BOT" at 10545.23,29.32 h40.89
  text "Pad" at 11359.69,29.32 h40.89
  text "+/-3.00mil" at 11765.42,29.32 h40.89
  text "11" at 8972.57,-72.9 h40.89
  text "41.34mil (1.050mm)" at 9410.93,-72.9 h40.89
  text "PTH" at 10196.72,-72.9 h40.89
  text "L1-Top - L4-BOT" at 10545.23,-72.9 h40.89
  text "Pad" at 11359.69,-72.9 h40.89
  text "+/-3.00mil" at 11765.42,-72.9 h40.89
  text "3" at 8972.57,-175.11 h40.89
  text "59.06mil (1.500mm)" at 9410.93,-175.11 h40.89
  text "PTH" at 10196.72,-175.11 h40.89
  text "L1-Top - L4-BOT" at 10545.23,-175.11 h40.89
  text "Pad" at 11359.69,-175.11 h40.89
  text "+/-3.00mil" at 11765.42,-175.11 h40.89
  text "2" at 8972.57,-277.33 h40.89
  text "61.02mil (1.550mm)" at 9410.93,-277.33 h40.89
  text "NPTH" at 10196.72,-277.33 h40.89
  text "L1-Top - L4-BOT" at 10545.23,-277.33 h40.89
  text "Pad" at 11359.69,-277.33 h40.89
  text "+/-3.00mil" at 11765.42,-277.33 h40.89
  text "11" at 8972.57,-379.54 h40.89
  text "65.00mil (1.651mm)" at 9410.93,-379.54 h40.89
  text "PTH" at 10196.72,-379.54 h40.89
  text "L1-Top - L4-BOT" at 10545.23,-379.54 h40.89
  text "Pad" at 11359.69,-379.54 h40.89
  text "+/-3.00mil" at 11765.42,-379.54 h40.89
  text "6" at 8972.57,-481.75 h40.89
  text "70.87mil (1.800mm)" at 9410.93,-481.75 h40.89
  text "PTH" at 10196.72,-481.75 h40.89
  text "L1-Top - L4-BOT" at 10545.23,-481.75 h40.89
  text "Pad" at 11359.69,-481.75 h40.89
  text "+/-3.00mil" at 11765.42,-481.75 h40.89
  text "G" at 8603.42,-489.75 h45.43
  text "12" at 8972.57,-583.97 h40.89
  text "78.74mil (2.000mm)" at 9410.93,-583.97 h40.89
  text "NPTH" at 10196.72,-583.97 h40.89
  text "L1-Top - L4-BOT" at 10545.23,-583.97 h40.89
  text "Pad" at 11359.69,-583.97 h40.89
  text "+/-3.00mil" at 11765.42,-583.97 h40.89
  text "C" at 8603.42,-591.96 h45.43
  text "2" at 8972.57,-686.18 h40.89
  text "118.11mil (3.000mm)" at 9410.93,-686.18 h40.89
  text "NPTH" at 10196.72,-686.18 h40.89
  text "L1-Top - L4-BOT" at 10545.23,-686.18 h40.89
  text "Pad" at 11359.69,-686.18 h40.89
  text "+/-3.00mil" at 11765.42,-686.18 h40.89
  text "E" at 8603.42,-694.18 h45.43
  text "2" at 8972.57,-788.4 h40.89
  text "125.20mil (3.180mm)" at 9410.93,-788.4 h40.89
  text "PTH" at 10196.72,-788.4 h40.89
  text "L1-Top - L4-BOT" at 10545.23,-788.4 h40.89
  text "Pad" at 11359.69,-788.4 h40.89
  text "+/-3.00mil" at 11765.42,-788.4 h40.89
  text "4" at 8972.57,-890.61 h40.89
  text "125.98mil (3.200mm)" at 9410.93,-890.61 h40.89
  text "PTH" at 10196.72,-890.61 h40.89
  text "L1-Top - L4-BOT" at 10545.23,-890.61 h40.89
  text "Pad" at 11359.69,-890.61 h40.89
  text "+/-3.00mil" at 11765.42,-890.61 h40.89
  text "4" at 8972.57,-992.82 h40.89
  text "137.79mil (3.500mm)" at 9410.93,-992.82 h40.89
  text "NPTH" at 10196.72,-992.82 h40.89
  text "L1-Top - L4-BOT" at 10545.23,-992.82 h40.89
  text "Pad" at 11359.69,-992.82 h40.89
  text "+/-3.00mil" at 11765.42,-992.82 h40.89
  text "4" at 8972.57,-1095.04 h40.89
  text "137.79mil (3.500mm)" at 9410.93,-1095.04 h40.89
  text "PTH" at 10196.72,-1095.04 h40.89
  text "L1-Top - L4-BOT" at 10545.23,-1095.04 h40.89
  text "Pad" at 11359.69,-1095.04 h40.89
  text "+/-3.00mil" at 11765.42,-1095.04 h40.89
  text "1014 Total" at 8972.57,-1197.25 h40.89
  text "Slot definitions :" at 8624.06,-1298.41 h40.89
  text "Routed Path Length" at 9331.08,-1298.41 h40.89
  text "= Calculated from tool start centre position to tool end centre position." at 10085.78,-1298.41 h40.89
  text "Hole Length" at 9331.08,-1368.91 h40.89
  text "= Routed Path Length + Tool Size = Slot length as defined in the PCB layout" at 9806.49,-1368.91 h40.89
Doc-Assy-Top:
  lines w5.2: 5124.12,-2166.68 5124.12,-1424.52 8243.15,-1424.52 ; 5124.12,-1916.22 8243.15,-1916.22 ; 5594.81,-2166.68 5594.81,-1916.22 ; 6325.07,-2166.68 6325.07,-1916.22 ; 6471.08,-1915.91 6471.08,-1424.52 ; 7404.58,-2166.68 7404.58,-1916.22
  lines w5.21: -2584.85,-370.83 -2376.61,-370.83 ; -2584.85,1841.8 -2376.61,1841.8 ; -2584.85,4054.43 -2376.61,4054.43 ; 70.3,-2375.21 70.3,-2166.96 ; 70.3,5850.56 70.3,6058.81 ; 2933.7,-2375.21 2933.7,-2166.96 ; 2933.7,5850.56 2933.7,6058.81 ; 3766.69,-2375.21 8452.25,-2375.21 ; 5797.1,-2375.21 5797.1,-2166.96 ; 5797.1,5850.56 5797.1,6058.81 ; 8244.01,-370.83 8452.25,-370.83 ; 8244.01,1841.8 8452.25,1841.8 ; 8244.01,4054.43 8452.25,4054.43 ; 8452.25,-2375.21 -2584.85,-2375.21 -2584.85,6058.81 8452.25,6058.81 8452.25,-2375.21 ; -2376.61,-2166.96 8244.01,-2166.96 8244.01,5850.56 -2376.61,5850.56 -2376.61,-2166.96
  text "1" at -1386.04,5921.52 h72.89
  text "2" at 1478.05,5921.52 h72.89
  text "3" at 4336.25,5921.52 h72.89
  text "4" at 7200.7,5921.52 h72.89
  text "A" at -2510.04,5066.51 h72.89
  text "A" at 8325.38,5066.51 h72.89
  text "B" at -2510.04,2853.88 h72.89
  text "B" at 8325.38,2853.88 h72.89
  text "C" at -2510.04,641.25 h72.89
  text "C" at 8325.38,641.25 h72.89
  text "TITLE:" at 5204.95,-1506.47 h46.83
  text "Opal Kelly" at 6553.03,-1539.25 h72.85
  text "D" at -2510.04,-1566.17 h72.89
  text "D" at 8325.38,-1566.17 h72.89
  text "13500 SW 72nd Ave Suite 100" at 6553.03,-1662.18 h72.85
  text "Portland, OR 97223" at 6553.03,-1764.62 h72.85
  text "'.Part_Number' / Assembly Drawing" at 5238.64,-1766.37 h72.85
  text "www.opalkelly.com" at 6553.03,-1867.05 h72.85
  text "(Top)" at 5238.64,-1885.02 h72.85
  text "REV:" at 5182.05,-1985.62 h46.83
  text "SIZE:" at 5658.31,-1985.62 h46.83
  text "ENGINEER:" at 6388.57,-1985.62 h46.83
  text "DATE:" at 7468.09,-1985.62 h46.83
  text "'.PCB_Revision'XX" at 5245.55,-2112.62 h72.85
  text "ANSI A" at 5721.81,-2112.62 h72.85
  text "RCA" at 6452.07,-2112.62 h72.85
  text ".PRINT_DATE" at 7531.59,-2112.62 h72.85
  text "1" at -1386.04,-2310.81 h72.89
  text "2" at 1478.05,-2310.81 h72.89
  text "3" at 4336.25,-2310.81 h72.89
  text "4" at 7200.7,-2310.81 h72.89
Doc-Assy-Bot:
  lines w5.2: -2376.76,-1915.24 742.64,-1915.24 ; -2376.76,-1423.48 742.64,-1423.48 742.64,-2165.72 ; -1538.1,-2165.72 -1538.1,-1915.24 ; -604.48,-1914.93 -604.48,-1423.48 ; -458.46,-2165.72 -458.46,-1915.24 ; 271.89,-2165.72 271.89,-1915.24
  lines w5.21: -2585.9,-369.66 -2377.63,-369.66 ; -2585.9,1843.24 -2377.63,1843.24 ; -2585.9,4056.13 -2377.63,4056.13 ; 69.58,-2374.28 69.58,-2166.01 ; 69.58,5852.48 69.58,6060.76 ; 2100.23,-2374.28 -2585.9,-2374.28 ; 2933.32,-2374.28 2933.32,-2166.01 ; 2933.32,5852.48 2933.32,6060.76 ; 5797.07,-2374.28 5797.07,-2166.01 ; 5797.07,5852.48 5797.07,6060.76 ; 8244.27,-369.66 8452.54,-369.66 ; 8244.27,1843.24 8452.54,1843.24 ; 8244.27,4056.13 8452.54,4056.13 ; -2585.9,-2374.28 -2585.9,6060.76 8452.54,6060.76 8452.54,-2374.28 -2585.9,-2374.28 ; -2377.63,-2166.01 -2377.63,5852.48 8244.27,5852.48 8244.27,-2166.01 -2377.63,-2166.01
  text "4" at -1334.19,5923.45 h72.9
  text "3" at 1530.61,5923.45 h72.9
  text "2" at 4389.15,5923.45 h72.9
  text "1" at 7253.58,5923.45 h72.9
  text "A" at -2459.01,5068.34 h72.9
  text "A" at 8377.72,5068.34 h72.9
  text "B" at -2459.01,2855.44 h72.9
  text "B" at 8377.72,2855.44 h72.9
  text "C" at -2459.01,642.55 h72.9
  text "C" at 8377.72,642.55 h72.9
  text "TITLE:" at 661.8,-1505.44 h46.84
  text "Opal Kelly" at -686.44,-1538.22 h72.86
  text "D" at -2459.01,-1565.14 h72.9
  text "D" at 8377.72,-1565.14 h72.9
  text "13500 SW 72nd Ave Suite 100" at -686.44,-1661.16 h72.86
  text "Portland, OR 97223" at -686.44,-1763.61 h72.86
  text "'.Part_Number' / Assembly Drawing" at 628.11,-1765.37 h72.86
  text "www.opalkelly.com" at -686.44,-1866.06 h72.86
  text "(Bottom)" at 628.11,-1884.03 h72.86
  text "DATE:" at -1601.61,-1984.64 h46.84
  text "ENGINEER:" at -521.96,-1984.64 h46.84
  text "SIZE:" at 208.38,-1984.64 h46.84
  text "REV:" at 684.7,-1984.64 h46.84
  text ".PRINT_DATE" at -1665.12,-2111.66 h72.86
  text "RCA" at -585.47,-2111.66 h72.86
  text "ANSI A" at 144.88,-2111.66 h72.86
  text "'.PCB_Revision'XX" at 621.19,-2111.66 h72.86
  text "4" at -1334.19,-2309.87 h72.9
  text "3" at 1530.61,-2309.87 h72.9
  text "2" at 4389.15,-2309.87 h72.9
  text "1" at 7253.58,-2309.87 h72.9
Doc-Fab:
  lines w5: 8825.96,-2462.5 8825.96,-1406.36 13365.15,-1406.36 ; 8825.96,-1596.36 10585.96,-1596.36 ; 8825.96,-1486.36 10585.96,-1486.36 ; 9245.96,-2462.5 9245.96,-1406.36 ; 10585.96,-2462.5 10585.96,-1406.36 ; 10585.96,-2266.36 13365.96,-2266.36 ; 10585.96,-1826.36 13365.15,-1826.36 ; 11145.96,-2462.5 11145.96,-2266.36 ; 11825.96,-2266.36 11825.96,-1826.36 ; 12475.96,-2462.5 12475.96,-2266.36
  lines w5.49: -2897.87,-74.18 -2678.09,-74.18 ; -2897.87,2535.76 -2678.09,2535.76 ; -2897.87,5145.7 -2678.09,5145.7 ; -150.56,-2684.12 -150.56,-2464.34 ; -150.56,7535.85 -150.56,7755.64 ; 2596.74,-2684.12 2596.74,-2464.34 ; 2596.74,7535.85 2596.74,7755.64 ; 5344.05,-2684.12 5344.05,-2464.34 ; 5344.05,7535.85 5344.05,7755.64 ; 8091.35,-2684.12 8091.35,-2464.34 ; 8091.35,7535.85 8091.35,7755.64 ; 10838.66,-2684.12 10838.66,-2464.34 ; 10838.66,7535.85 10838.66,7755.64 ; 13366.18,-74.18 13585.96,-74.18 ; 13366.18,2535.76 13585.96,2535.76 ; 13366.18,5145.7 13585.96,5145.7 ; -2897.87,-2684.12 13585.96,-2684.12 13585.96,7755.64 -2897.87,7755.64 -2897.87,-2684.12 ; -2678.09,-2464.34 13366.18,-2464.34 13366.18,7535.85 -2678.09,7535.85 -2678.09,-2464.34
  text "1" at -1544.73,7612.78 h76.92
  text "2" at 1197.81,7612.78 h76.92
  text "3" at 3933.41,7612.78 h76.92
  text "4" at 6688.04,7612.78 h76.92
  text "5" at 9434.23,7612.78 h76.92
  text "6" at 12187.03,7612.78 h76.92
  text "A" at -2815.45,6356.71 h76.92
  text "A" at 13448.6,6356.71 h76.92
  text "B" at -2815.45,3741.27 h76.92
  text "B" at 13448.6,3741.27 h76.92
  text "C" at -2815.45,1131.33 h76.92
  text "C" at 13448.6,1131.33 h76.92
  text "REVISION:" at 8854.96,-1466.36 h40
  text "DESCRIPTION:" at 9284.96,-1466.36 h40
  text "D" at -2815.45,-1473.11 h76.92
  text "D" at 13448.6,-1473.11 h76.92
  text "PART NUMBER:" at 10665.96,-1546.36 h75
  text "AXX" at 8855.96,-1566.36 h50
  text "Initial Release" at 9285.96,-1566.36 h50
  text "'.Part_Number'-PCB-'.PCB_Revision'XX" at 10685.96,-1826.36 h130
  text "TITLE:" at 10645.96,-1906.36 h40
  text "Opal Kelly" at 11885.96,-1926.36 h60
  text "13500 SW 72nd Ave Suite 100" at 11885.96,-2026.36 h60
  text "Portland, OR 97223" at 11885.96,-2126.36 h60
  text "'.Part_Number' / Fabrication Drawing" at 10685.96,-2206.36 h60
  text "www.opalkelly.com" at 11885.96,-2226.36 h60
  text "SIZE:" at 10645.96,-2326.36 h40
  text "ENGINEER:" at 11205.96,-2326.36 h40
  text "DATE:" at 12525.96,-2326.36 h40
  text "ANSI A" at 10685.96,-2426.36 h60
  text "RCA" at 11245.96,-2426.36 h60
  text ".PRINT_DATE" at 12565.96,-2426.36 h60
  text "1" at -1544.73,-2607.2 h76.92
  text "2" at 1197.81,-2607.2 h76.92
  text "3" at 3933.41,-2607.2 h76.92
  text "4" at 6688.04,-2607.2 h76.92
  text "5" at 9434.23,-2607.2 h76.92
  text "6" at 12187.03,-2607.2 h76.92

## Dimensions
10416.5,2088.51 to 10338.57,1939.51 on Fab Notes
10626.5,2073.51 to 10772.09,2088.51 on Fab Notes
10391.5,2127.88 to 10644.69,2310.01 on Fab Notes
10456.5,2083.51 to 10668.54,2224.48 on Fab Notes
10391.5,2167.25 to 10601.5,2167.25 on Fab Notes
-0.01,177.16 to 295.27,368.11 on Dimensions
-0.01,177.16 to 590.54,177.16 on Dimensions
590.54,177.16 to 1312.98,177.16 on Dimensions
2249.99,330.71 to 295.27,368.11 on Dimensions
2249.99,330.71 to -0.01,177.16 on Dimensions
2249.99,330.71 to 1771.65,19.68 on Dimensions
2249.99,330.71 to 3791.33,19.68 on Dimensions
2212.59,19.68 to 2287.39,19.68 on Dimensions
1771.65,19.68 to 2249.99,330.71 on Dimensions
590.54,501.97 to 590.54,177.16 on Dimensions
4638.85,-134.01 to 4687.73,-5.23 on Dimensions
4526.83,-267.19 to 4588.43,-266.84 on Dimensions
4688.68,-266.84 to 4588.43,-321.84 on Dimensions
1627.94,177.16 to 1771.65,19.68 on Dimensions
1312.98,177.16 to 1771.65,19.68 on Dimensions
295.27,368.11 to 295.27,3730.31 on Dimensions
-0.01,4139.76 to 5944.88,4139.76 on Dimensions
-0.01,177.16 to -0.01,4139.76 on Dimensions
1761.8,-9.84 to -0.01,4139.76 on Dimensions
